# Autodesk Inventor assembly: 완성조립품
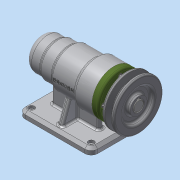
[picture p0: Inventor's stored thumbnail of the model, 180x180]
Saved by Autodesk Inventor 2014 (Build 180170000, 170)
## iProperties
Created: 2016-06
Part Number: 완성조립품
Document SubType Name: Assembly
Designer: 406-017
Author: 406-017
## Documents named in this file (12)
- C:\Users\406-017\Desktop\460607V1015\완성조립품.iam
- C:\Users\406-017\Desktop\460607V1015\V벨트풀리.ipt
- C:\Users\406-017\Desktop\460607V1015\멈춤나사 M3x8.ipt
- C:\Users\406-017\Desktop\460607V1015\베어링 6004.ipt
- C:\Users\406-017\Desktop\460607V1015\베어링 51202.ipt
- C:\Users\406-017\Desktop\460607V1015\본체.ipt
- C:\Users\406-017\Desktop\460607V1015\볼트 M4 x 12.ipt
- C:\Users\406-017\Desktop\460607V1015\어댑터슬리브.ipt
- C:\Users\406-017\Desktop\460607V1015\오일 실.ipt
- C:\Users\406-017\Desktop\460607V1015\축.ipt
- C:\Users\406-017\Desktop\460607V1015\커버.ipt
- C:\Users\406-017\Desktop\460607V1015\키 5 x 5 x 16.ipt
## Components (6 placed, 2 different names)
1. V벨트풀리:1 — 플러쉬:1, 각도:2
2. ISO 4762 M4 x 12:2 — 플러쉬:2
3. ISO 4762 M4 x 12:1
4. ISO 4762 M4 x 12:3
5. ISO 4762 M4 x 12:4
6. ISO 4762 M4 x 12:5
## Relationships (3: Flush 2, Angle 1)
- 플러쉬:1 [Flush]: V벨트풀리:1
- 플러쉬:2 [Flush]: ISO 4762 M4 x 12:2
- 각도:2 [Angle]: V벨트풀리:1
